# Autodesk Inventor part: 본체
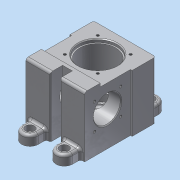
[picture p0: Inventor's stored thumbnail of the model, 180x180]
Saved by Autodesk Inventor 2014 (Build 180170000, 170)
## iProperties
Created: 2024-11
Part Number: 본체
Material: 알루미늄 6061
Document SubType Name: Modeling
Designer: dg
Density: 2.71 g/cm^3
Appearance: 알루미늄 - 평지
Mass: 806.38 g
Surface Area: 539.693 cm^2
Volume: 297.557 cm^3
Author: dg
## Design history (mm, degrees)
sketch "스케치1"
  geometry: L1 (-38, 42.5)-(38, 42.5); L2 (38, 42.5)-(38, -42.5); L3 (38, -42.5)-(-38, -42.5); L4 (-38, -42.5)-(-38, 42.5); 3 further points
  constraints: 8 end point, 2 midpoint, 2 parallel, 1 horizontal, 1 horizontal alignment, 1 perpendicular, 1 vertical alignment
  dimensions: "d0" = 85 distance of L3.end L1.start; "d1" = 76 distance of L1.start L1.end
extrude "돌출1" new body sketch "스케치1" distance "d2" = 74; taper "d3" = 0 deg
sketch "스케치3"
  geometry: L1 (0, 74)-(0, 0) reference; L2 (76, 0)-(0, 0); L3 (0, 0)-(0, 4); L4 (0, 4)-(76, 4); L5 (76, 4)-(76, 0); 1 further point
  constraints: 8 end point, 2 parallel, 1 horizontal, 1 perpendicular, 1 point on line
  dimensions: "d9" = 4 distance between parallel lines of L4 L2
extrude "돌출3" cut sketch "스케치3" distance "d10" = 66; taper "d11" = 0 deg
sketch "스케치4"
  geometry: L1 (-23.5, 70)-(42.5, 70) reference; L2 (42.5, 70)-(42.5, 0) reference; L3 (42.5, 0)-(-42.5, 0) reference; L4 (-42.5, 0)-(-42.5, 74) reference; L5 (-42.5, 74)-(-23.5, 74) reference; L6 (-23.5, 74)-(-23.5, 70) reference; L7 (0, 70)-(23.5, 70); L8 (17.5, 4.172)-(15, 4.172); L9 (15, 4.172)-(15, 2.472); 1 further point
  constraints: 6 end point, 2 point on line, 1 perpendicular
  node "절단 모서리 투영1"
sketch "스케치9"
  geometry: L1 (76, -74)-(0, -74) reference; L2 (0, 0)-(2, 0); L3 (2, 0)-(2, -74); L4 (2, -74)-(0, -74); L5 (0, -74)-(0, 0); 2 further points
  constraints: 8 end point, 2 parallel, 1 horizontal, 1 perpendicular, 1 point on line
  dimensions: "d30" = 2 distance of L2.start L2.end
extrude "돌출8" cut sketch "스케치9" distance "d31" = 56; taper "d32" = 0 deg
sketch "스케치10"
  geometry: L1 (38, 42.5)-(-38, 42.5) reference; L2 (-31, 52.5)-(-31, 42.5); L3 (-11, 52.5)-(-11, 42.5); A1 r 10 centre (-21, 52.5) between (-11, 52.5) and (-31, 52.5); 1 further point
  constraints: 4 end point, 2 perpendicular, 2 point on circle, 2 point on line, 2 tangent, 1 centre point
  dimensions: "d36" = 20 diameter of A1; "d37" = 21 horizontal distance of point (0, 0) A1.centre; "d38" = 10 distance from line of L1 A1.centre
extrude "돌출9" join sketch "스케치10" distance "d39" = 12; taper "d40" = 0 deg
hole "구멍1" diameter "d43" = 6.6; stored, may be unused: countersink angle "d47" = 90 deg, drill point angle "d49" = 118 deg; dims "d41" = 10, "d42" = 10, "d44" = 6, "d45" = 11, "d46" = 6.6, "d48" = 8
sketch "스케치12"
  geometry: L1 (42.5, 70)-(42.5, 0) reference; L2 (42.5, 0)-(-42.5, 0) reference; L3 (-42.5, 0)-(-42.5, 74) reference; L4 (-42.5, 74)-(-23.5, 74) reference; L5 (-23.5, 74)-(-23.5, 70) reference; L6 (-23.5, 70)-(42.5, 70) reference; L7 (9.5, 70)-(9.5, 0); L8 (33, 70)-(33, 66); L9 (33, 66)-(31.5, 66); L10 (31.5, 66)-(31.5, 21); L11 (28.5, 18)-(27, 18); L12 (27, 18)-(27, 7.6); L13 (26.4, 7)-(24.5, 7); L14 (24.5, 7)-(24.5, 7); L15 (21.5, 4)-(9.5, 4); A1 r 3 centre (28.5, 21) between (28.5, 18) and (31.5, 21); A2 r 0.6 centre (26.4, 7.6) between (26.4, 7) and (27, 7.6); A3 r 3 centre (21.5, 7) between (21.5, 4) and (24.5, 7); 3 further points
  constraints: 18 end point, 7 point on line, 6 point on circle, 6 tangent, 5 perpendicular, 3 centre point, 3 parallel, 1 equal radius, 1 midpoint, 1 vertical
  dimensions: "d55" = 33 distance between parallel lines of L7 L1; "d56" = 47 diameter of L8 L7; "d57" = 44 diameter of L10 L7; "d58" = 35 diameter of L12 L7; "d59" = 30 diameter of L14 L7; "d60" = 4 distance of L8.start L8.end; "d61" = 56 distance between parallel lines of L11 L4; "d62" = 11 distance of L11.end point (27, 7); "d63" = 3 distance of L13.end point (24.5, 4); "d64" = 3 radius of A1; "d65" = 0.6 radius of A2
revolve "회전1" sketch "스케치12" stored, may be unused: angle "d66" = 90 deg
sketch "스케치13"
  geometry: L1 (0, -10)-(0, 0) reference; L2 (0, 85)-(70, 85) reference; C1 r 16.5 at (42, 28); 1 further point
  constraints: 1 centre point
  dimensions: "d67" = 42 distance from line of C1.centre L1; "d68" = 33 diameter of C1; "d69" = 57 distance from line of C1.centre L2
extrude "돌출11" cut sketch "스케치13" stored distance "d70" = 12; taper "d71" = 0 deg
sketch "스케치14" dims "d72" = 57
  geometry: L1 (38, -33)-(52.157, -33); L2 (58.153, -12.847)-(38, -33); C1 r 23.5 at (38, -33) reference; 1 further point
  constraints: 4 end point, 1 coincident, 1 horizontal, 3 other
  dimensions: "d73" = 45 deg angle of L1 L2
hole "구멍2" sketch "스케치14" at (58.153, -12.847) diameter "d74" = 3.242; stored, may be unused: countersink angle "d78" = 90 deg, drill point angle "d80" = 118 deg; dims "d75" = 8, "d76" = 11, "d77" = 6.6, "d79" = 10
sketch "스케치15"
  geometry: C1 r 16.5 at (42, 28) reference; 5 further points
  constraints: 2 horizontal alignment, 2 vertical alignment
  dimensions: "d84" = 32 distance of point (26, 12) point (26, 44); "d85" = 16 horizontal distance of point (26, 12) C1.centre; "d86" = 32 distance of point (58, 12) point (26, 12); "d87" = 16 horizontal distance of point (58, 12) C1.centre
hole "구멍3" sketch "스케치15" at (26, 44), (26, 12), (58, 44), (58, 12) diameter "d88" = 3.242; stored, may be unused: countersink angle "d92" = 90 deg, drill point angle "d94" = 118 deg; dims "d89" = 8, "d90" = 11, "d91" = 6.6, "d93" = 10
fillet "모깎기1" dims "d95" = 3
sketch "스케치16"
  geometry: L1 (-36, -42.5)-(36, -42.5) reference; L2 (-6, -42.5)-(6, -42.5); L3 (6, -42.5)-(6, -27.5); L4 (6, -27.5)-(-6, -27.5); L5 (-6, -27.5)-(-6, -42.5); 3 further points
  constraints: 8 end point, 2 midpoint, 2 parallel, 1 coincident, 1 horizontal, 1 perpendicular, 1 vertical alignment
  dimensions: "d96" = 12 distance of L3.end L4.end; "d97" = 15 distance between parallel lines of L4 L1
extrude "돌출12" cut sketch "스케치16" stored distance "d98" = 12; taper "d99" = 0 deg
fillet "모깎기3" dims "d101" = 3
fillet "모깎기4" dims "d102" = 3
chamfer "모따기1" distance "d103" = 1; stored, may be unused: second distance "d104" = 2, angle "d105" = 45 deg
sketch "스케치17"
  geometry: L1 (27, 70)-(43, 70) reference; L2 (0, 0)-(70, 0) reference; 3 further points
  constraints: 1 midpoint, 1 vertical alignment, 1 other
  dimensions: "d106" = 20 distance from line of point (35, 20) L2
feature "엠보싱1" sketch "스케치17" dims "d0" = 85, "d1" = 76, "d107" = 0.5, "d108" = 0
sketch "스케치18"
  geometry: L1 (0, 0)-(12, 0) reference; L2 (12, -74)-(0, -74) reference; 5 further points
  constraints: 2 midpoint, 2 vertical alignment
  dimensions: "d109" = 12 distance from line of L1 point (6, -12); "d110" = 40 distance of point (6, -12) point (6, -52)
hole "구멍4" sketch "스케치18" at (6, -12), (6, -52) diameter "d111" = 3.242; stored, may be unused: countersink angle "d115" = 90 deg, drill point angle "d117" = 118 deg; dims "d112" = 8, "d113" = 11, "d114" = 6.6, "d116" = 10
chamfer "모따기2" distance "d118" = 1; stored, may be unused: second distance "d119" = 2, angle "d120" = 45 deg
fillet "모깎기5" dims "d121" = 3
chamfer "모따기3" distance "d122" = 1; stored, may be unused: second distance "d123" = 2, angle "d124" = 45 deg
node "솔리드1"
mirror "대칭1"
mirror "대칭2"
mirror "대칭3"
pattern_circular "원형 패턴1" dims angle "d82" = 360 deg
mirror "대칭4"
node "절단 모서리 투영4"
